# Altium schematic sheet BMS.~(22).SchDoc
size A3; SheetNumber: 3; SheetTotal: 3
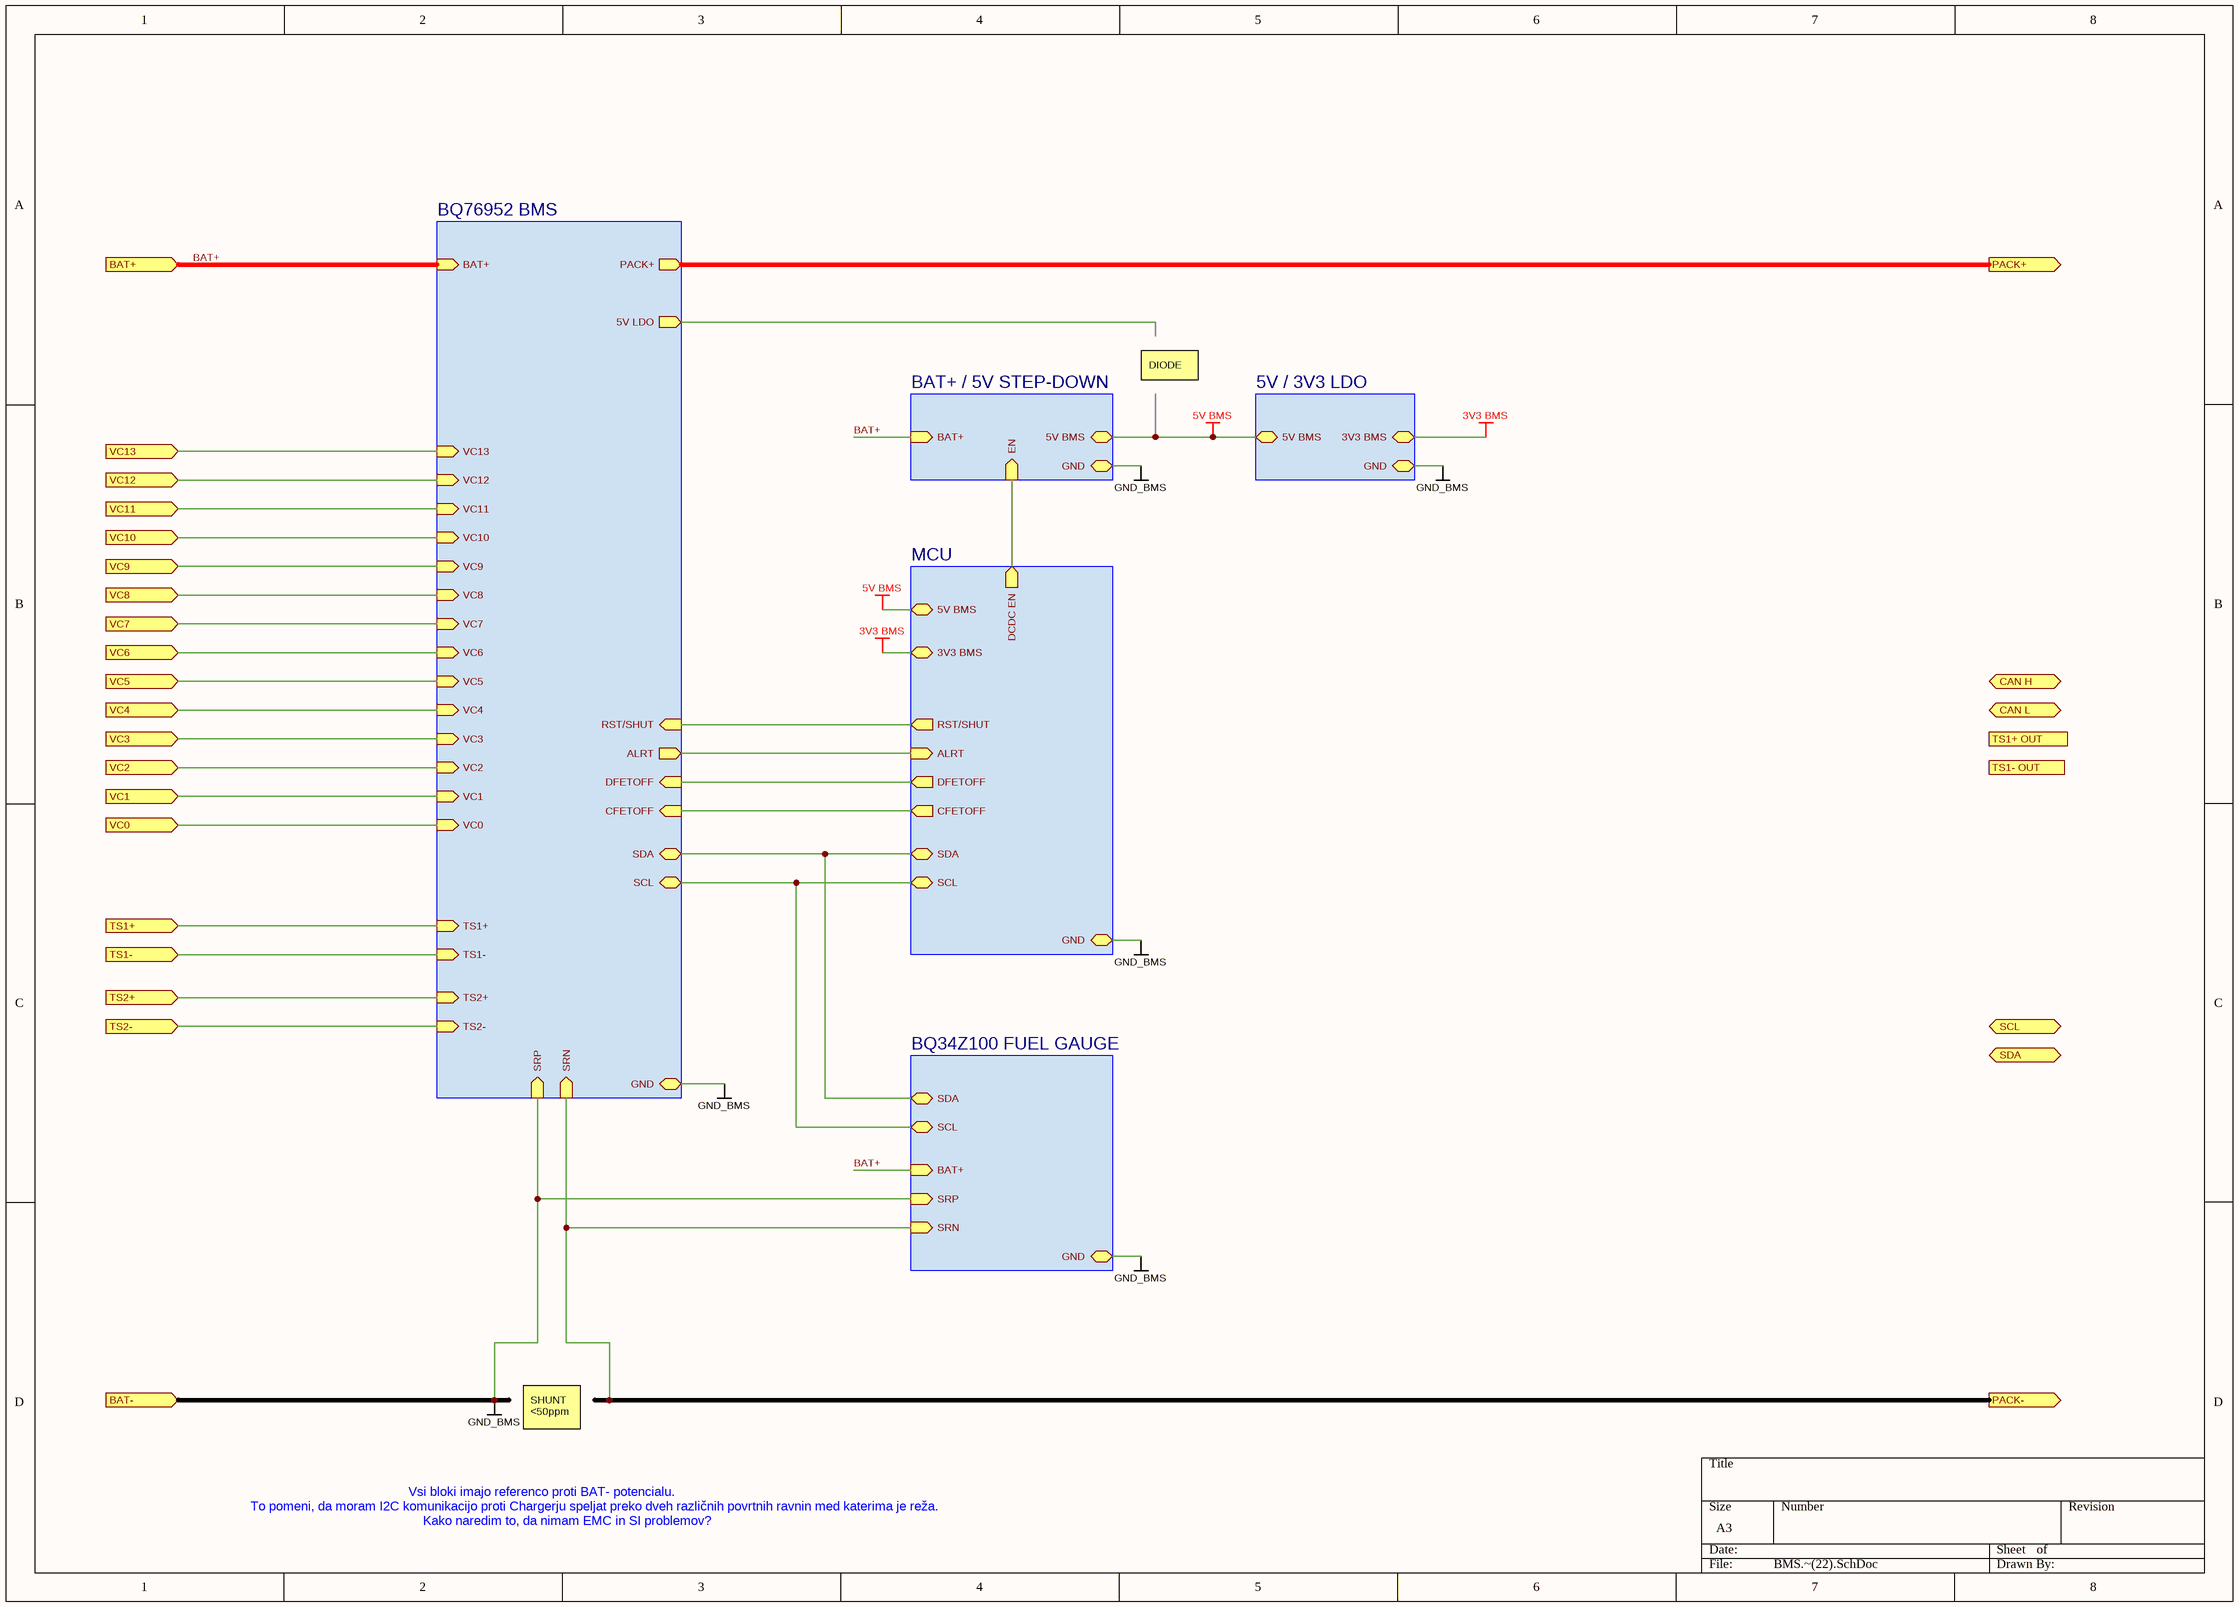
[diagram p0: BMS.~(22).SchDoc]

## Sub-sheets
5V / 3V3 LDO = 5V / 3V3 LDO.SchDoc: 5V BMS (bidir), 3V3 BMS (bidir), GND (bidir)
BAT+ / 5V STEP-DOWN = BAT+ / 5V STEP-DOWN.SchDoc: 5V BMS (bidir), BAT+ (in), EN (in), GND (bidir)
BQ34Z100 FUEL GAUGE = BQ34Z100 FUEL GAUGE.SchDoc: SRP (in), SRN (in), SDA (bidir), SCL (bidir), BAT+ (in), GND (bidir)
BQ76952 BMS = BQ76952 BMS.SchDoc: VC13 (in), VC12 (in), VC11 (in), VC10 (in), VC9 (in), VC8 (in), VC7 (in), VC6 (in), VC5 (in), VC4 (in), VC3 (in), VC2 (in), VC1 (in), VC0 (in), TS1+ (in), TS1- (in), TS2+ (in), TS2- (in), BAT+ (in), PACK+ (out), 5V LDO (out), SRP (in), SRN (in), SDA (bidir), SCL (bidir), ALRT (out), DFETOFF (in), CFETOFF (in), RST/SHUT (in), GND (bidir)
MCU = MCU.SchDoc: DCDC EN (out), 5V BMS (bidir), 3V3 BMS (bidir), SDA (bidir), SCL (bidir), ALRT (in), DFETOFF (out), CFETOFF (out), RST/SHUT (out), GND (bidir)

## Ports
BAT+ (in, see Arhitecture[3B]), BAT- (in, see Arhitecture[3C]), CAN H (bidir, see Arhitecture[4B]), CAN L (bidir, see Arhitecture[4B]), PACK+ (out, see Arhitecture[4C], CHARGER[1B]), PACK- (out, see Arhitecture[4C], CHARGER[1C]), SCL (bidir, see Arhitecture[4C], CHARGER[1D]), SDA (bidir, see Arhitecture[4C], CHARGER[1D]), TS1+ (in, see Arhitecture[3C]), TS1+ OUT (out, see Arhitecture[4C]), TS1- (in, see Arhitecture[3C]), TS1- OUT (out, see Arhitecture[4C]), TS2+ (in, see Arhitecture[3C]), TS2- (in, see Arhitecture[3C]), VC0 (in, see Arhitecture[3C]), VC1 (in, see Arhitecture[3C]), VC2 (in, see Arhitecture[3C]), VC3 (in, see Arhitecture[3C]), VC4 (in, see Arhitecture[3C]), VC5 (in, see Arhitecture[3C]), VC6 (in, see Arhitecture[3B]), VC7 (in, see Arhitecture[3B]), VC8 (in, see Arhitecture[3B]), VC9 (in, see Arhitecture[3B]), VC10 (in, see Arhitecture[3B]), VC11 (in, see Arhitecture[3B]), VC12 (in, see Arhitecture[3B]), VC13 (in, see Arhitecture[3B])

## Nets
3V3 BMS: sheet MCU/3V3 BMS, sheet 5V / 3V3 LDO/3V3 BMS
5V BMS: sheet MCU/5V BMS, sheet BAT+ / 5V STEP-DOWN/5V BMS, sheet 5V / 3V3 LDO/5V BMS
GND_BMS: port BAT-, sheet BQ76952 BMS/SRP, sheet BQ76952 BMS/GND, sheet BQ34Z100 FUEL GAUGE/SRP, sheet BQ34Z100 FUEL GAUGE/GND, sheet MCU/GND, sheet BAT+ / 5V STEP-DOWN/GND, sheet 5V / 3V3 LDO/GND
BAT+: port BAT+, sheet BQ76952 BMS/BAT+, sheet BQ34Z100 FUEL GAUGE/BAT+, sheet BAT+ / 5V STEP-DOWN/BAT+
PACK+: port PACK+, sheet BQ76952 BMS/PACK+
PACK-: port PACK-, sheet BQ76952 BMS/SRN, sheet BQ34Z100 FUEL GAUGE/SRN
TS1+: port TS1+, sheet BQ76952 BMS/TS1+
TS1-: port TS1-, sheet BQ76952 BMS/TS1-
TS2+: port TS2+, sheet BQ76952 BMS/TS2+
TS2-: port TS2-, sheet BQ76952 BMS/TS2-
VC0: port VC0, sheet BQ76952 BMS/VC0
VC1: port VC1, sheet BQ76952 BMS/VC1
VC2: port VC2, sheet BQ76952 BMS/VC2
VC3: port VC3, sheet BQ76952 BMS/VC3
VC4: port VC4, sheet BQ76952 BMS/VC4
VC5: port VC5, sheet BQ76952 BMS/VC5
VC6: port VC6, sheet BQ76952 BMS/VC6
VC7: port VC7, sheet BQ76952 BMS/VC7
VC8: port VC8, sheet BQ76952 BMS/VC8
VC9: port VC9, sheet BQ76952 BMS/VC9
VC10: port VC10, sheet BQ76952 BMS/VC10
VC11: port VC11, sheet BQ76952 BMS/VC11
VC12: port VC12, sheet BQ76952 BMS/VC12
VC13: port VC13, sheet BQ76952 BMS/VC13
(unnamed): sheet BQ76952 BMS/SDA, sheet BQ34Z100 FUEL GAUGE/SDA, sheet MCU/SDA
(unnamed): sheet BQ76952 BMS/SCL, sheet BQ34Z100 FUEL GAUGE/SCL, sheet MCU/SCL  [a separate net that carries the same name]
(unnamed): sheet BQ76952 BMS/ALRT, sheet MCU/ALRT  [a separate net that carries the same name]
(unnamed): sheet BQ76952 BMS/DFETOFF, sheet MCU/DFETOFF  [a separate net that carries the same name]
(unnamed): sheet BQ76952 BMS/CFETOFF, sheet MCU/CFETOFF  [a separate net that carries the same name]
(unnamed): sheet BQ76952 BMS/RST/SHUT, sheet MCU/RST/SHUT  [a separate net that carries the same name]
(unnamed): sheet MCU/DCDC EN, sheet BAT+ / 5V STEP-DOWN/EN  [a separate net that carries the same name]

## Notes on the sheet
- DIODE
- SHUNT
  <50ppm
- To pomeni, da moram I2C komunikacijo proti Chargerju speljat preko dveh različnih povrtnih ravnin med katerima je reža.
- Vsi bloki imajo referenco proti BAT- potencialu.
- Kako naredim to, da nimam EMC in SI problemov?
